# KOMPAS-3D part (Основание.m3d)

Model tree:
1. Плоскость XY
2. Плоскость ZX
3. Плоскость ZY
4. Ось X
5. Ось Y
6. Ось Z
7. Начало координат
8. Эскиз:1
9. Операция выдавливания:1
     Расстояние 1 = 11.5; Расстояние 2 = 10
10. Эскиз:3
11. Вырезать элемент выдавливания:1
     Расстояние 2 = 10; Расстояние 1 = 9
12. Эскиз:4
13. Операция выдавливания:2
     Расстояние 1 = 5; Расстояние 2 = 10
14. Эскиз:5
15. Вырезать элемент выдавливания:2
     Расстояние 2 = 10; Расстояние 1 = 1.5
16. Эскиз:6
17. Вырезать элемент выдавливания:3
     Расстояние 2 = 10; Расстояние 1 = 2.5
18. Эскиз:8
19. Вырезать элемент выдавливания:4
     Расстояние 2 = 10; Расстояние 1 = 2; Угол 1 = 45

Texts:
  Линия-выноска #1
  Линия-выноска #2
  Линия-выноска #3
  Отклонения формы и база
  Марка координационной оси
  Марка/позиционное обозначение с линией-выноской
  Марка/позиционное обозначение на линии
  Марка/позиционное обозначение без линии-выноски
  Текст на чертеже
